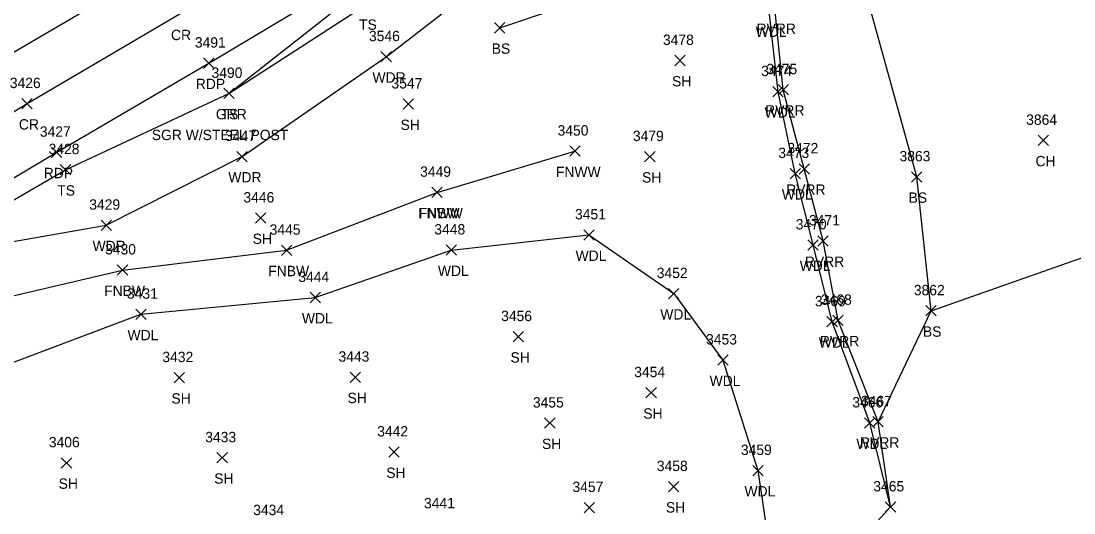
# Model space of a CAD drawing. Extents: x 1443590 to 1445966, y 578314 to 580556.
# Drawn here: x 1444092.8 to 1444295.6, y 578792.7 to 578887.6 of the extents above; entities that cross this region are included whole.
import ezdxf

# ---------------------------------------------------------------- set-up
doc = ezdxf.new("R2010")
doc.units = 0
for name, color, linetype in [('L_A', 7, 'Continuous'), ('L_I', 7, 'Continuous'), ('L_TIC', 7, 'Continuous'), ('LAWA', 7, 'Continuous'), ('LAWE', 7, 'Continuous'), ('LELB', 7, 'Continuous'), ('LFNC', 7, 'Continuous'), ('LSOGP', 7, 'Continuous'), ('P_A', 7, 'Continuous'), ('P_I', 7, 'Continuous'), ('P_TIC', 7, 'Continuous'), ('PET', 7, 'Continuous'), ('PRC', 7, 'Continuous'), ('R_A', 7, 'Continuous'), ('R_C', 7, 'Continuous'), ('R_I', 7, 'Continuous'), ('R_TIC', 7, 'Continuous'), ('RGR', 7, 'Continuous')]:
    doc.layers.add(name, color=color, linetype=linetype)

msp = doc.modelspace()

# ---------------------------------------------------------------- linework, layer by layer
at = {"layer": 'L_TIC'}
for points in [[(1444184, 578885.29), (1444186, 578887.29)], [(1444186, 578885.29), (1444184, 578887.29)], [(1444162.11, 578879.72), (1444164.11, 578881.72)], [(1444164.11, 578879.72), (1444162.11, 578881.72)], [(1444218.69, 578878.99), (1444220.69, 578880.99)], [(1444220.69, 578878.99), (1444218.69, 578880.99)], [(1444131.81, 578872.64), (1444133.81, 578874.64)], [(1444133.81, 578872.64), (1444131.81, 578874.64)], [(1444237.61, 578872.98), (1444239.61, 578874.98)], [(1444239.61, 578872.98), (1444237.61, 578874.98)], [(1444238.61, 578873.35), (1444240.61, 578875.35)], [(1444240.61, 578873.35), (1444238.61, 578875.35)], [(1444166.39, 578870.59), (1444168.39, 578872.59)], [(1444168.39, 578870.59), (1444166.39, 578872.59)], [(1444288.72, 578863.58), (1444290.72, 578865.58)], [(1444290.72, 578863.58), (1444288.72, 578865.58)], [(1444134.34, 578860.47), (1444136.34, 578862.47)], [(1444136.34, 578860.47), (1444134.34, 578862.47)], [(1444198.47, 578861.51), (1444200.47, 578863.51)], [(1444200.47, 578861.51), (1444198.47, 578863.51)], [(1444212.91, 578860.45), (1444214.91, 578862.45)], [(1444214.91, 578860.45), (1444212.91, 578862.45)], [(1444100.33, 578857.93), (1444102.33, 578859.93)], [(1444102.33, 578857.93), (1444100.33, 578859.93)], [(1444242.67, 578858.09), (1444244.67, 578860.09)], [(1444244.67, 578858.09), (1444242.67, 578860.09)], [(1444240.92, 578857.18), (1444242.92, 578859.18)], [(1444242.92, 578857.18), (1444240.92, 578859.18)], [(1444264.32, 578856.54), (1444266.32, 578858.54)], [(1444266.32, 578856.54), (1444264.32, 578858.54)], [(1444171.92, 578853.56), (1444173.92, 578855.56)], [(1444173.92, 578853.56), (1444171.92, 578855.56)], [(1444171.92, 578853.56), (1444173.92, 578855.56)], [(1444173.92, 578853.56), (1444171.92, 578855.56)], [(1444137.91, 578848.6), (1444139.91, 578850.6)], [(1444139.91, 578848.6), (1444137.91, 578850.6)], [(1444108.18, 578847.22), (1444110.18, 578849.22)], [(1444110.18, 578847.22), (1444108.18, 578849.22)], [(1444201.18, 578845.34), (1444203.18, 578847.34)], [(1444203.18, 578845.34), (1444201.18, 578847.34)], [(1444244.36, 578843.41), (1444246.36, 578845.41)], [(1444246.36, 578843.41), (1444244.36, 578845.41)], [(1444246.27, 578844.18), (1444248.27, 578846.18)], [(1444248.27, 578844.18), (1444246.27, 578846.18)], [(1444142.92, 578842.39), (1444144.92, 578844.39)], [(1444144.92, 578842.39), (1444142.92, 578844.39)], [(1444174.65, 578842.43), (1444176.65, 578844.43)], [(1444176.65, 578842.43), (1444174.65, 578844.43)], [(1444111.31, 578838.58), (1444113.31, 578840.58)], [(1444113.31, 578838.58), (1444111.31, 578840.58)], [(1444148.45, 578833.28), (1444150.45, 578835.28)], [(1444150.45, 578833.28), (1444148.45, 578835.28)], [(1444217.5, 578834.02), (1444219.5, 578836.02)], [(1444219.5, 578834.02), (1444217.5, 578836.02)], [(1444114.87, 578830.04), (1444116.87, 578832.04)], [(1444116.87, 578830.04), (1444114.87, 578832.04)], [(1444267.08, 578830.71), (1444269.08, 578832.71)], [(1444269.08, 578830.71), (1444267.08, 578832.71)], [(1444248.03, 578828.59), (1444250.03, 578830.59)], [(1444250.03, 578828.59), (1444248.03, 578830.59)], [(1444249.17, 578828.87), (1444251.17, 578830.87)], [(1444251.17, 578828.87), (1444249.17, 578830.87)], [(1444187.57, 578825.72), (1444189.57, 578827.72)], [(1444189.57, 578825.72), (1444187.57, 578827.72)], [(1444227, 578821.21), (1444229, 578823.21)], [(1444229, 578821.21), (1444227, 578823.21)], [(1444122.25, 578817.81), (1444124.25, 578819.81)], [(1444124.25, 578817.81), (1444122.25, 578819.81)], [(1444156.18, 578817.9), (1444158.18, 578819.9)], [(1444158.18, 578817.9), (1444156.18, 578819.9)], [(1444213.16, 578814.91), (1444215.16, 578816.91)], [(1444215.16, 578814.91), (1444213.16, 578816.91)], [(1444193.64, 578809.05), (1444195.64, 578811.05)], [(1444195.64, 578809.05), (1444193.64, 578811.05)], [(1444255.27, 578809.07), (1444257.27, 578811.07)], [(1444257.27, 578809.07), (1444255.27, 578811.07)], [(1444256.89, 578809.31), (1444258.89, 578811.31)], [(1444258.89, 578809.31), (1444256.89, 578811.31)], [(1444163.64, 578803.47), (1444165.64, 578805.47)], [(1444165.64, 578803.47), (1444163.64, 578805.47)], [(1444100.52, 578801.38), (1444102.52, 578803.38)], [(1444102.52, 578801.38), (1444100.52, 578803.38)], [(1444130.51, 578802.36), (1444132.51, 578804.36)], [(1444132.51, 578802.36), (1444130.51, 578804.36)], [(1444233.72, 578799.9), (1444235.72, 578801.9)], [(1444235.72, 578799.9), (1444233.72, 578801.9)], [(1444217.51, 578796.8), (1444219.51, 578798.8)], [(1444219.51, 578796.8), (1444217.51, 578798.8)], [(1444201.26, 578792.76), (1444203.26, 578794.76)], [(1444203.26, 578792.76), (1444201.26, 578794.76)], [(1444259.27, 578792.87), (1444261.27, 578794.87)], [(1444261.27, 578792.87), (1444259.27, 578794.87)]]:
    msp.add_lwpolyline(points, dxfattribs=at)
at = {"layer": 'LAWA'}
for points in [[(1444048.1, 578821.32), (1444063.67, 578832.31), (1444080.37, 578840.96), (1444085.34, 578844.04), (1444109.18, 578848.22), (1444135.34, 578861.47), (1444163.11, 578880.72), (1444179.57, 578893.49), (1444193.41, 578903.29), (1444214.9, 578918.81), (1444217.38, 578923.7), (1444222.65, 578929.51), (1444230.19, 578931.19), (1444234.32, 578936.96), (1444238.17, 578925.12), (1444234.94, 578915.96)], [(1444260.27, 578793.87), (1444256.27, 578810.07), (1444249.03, 578829.59), (1444245.36, 578844.41), (1444241.92, 578858.18), (1444238.61, 578873.98), (1444236.87, 578889.53), (1444235.77, 578897.72), (1444234.94, 578915.96)], [(1444048.1, 578821.32), (1444049.15, 578815.65), (1444053.76, 578808.6), (1444089.15, 578821), (1444115.87, 578831.04), (1444149.45, 578834.28), (1444175.65, 578843.43), (1444202.18, 578846.34), (1444218.5, 578835.02), (1444228, 578822.21), (1444234.72, 578800.9), (1444237.58, 578781.4), (1444240.48, 578772.04)]]:
    msp.add_lwpolyline(points, dxfattribs=at)
at = {"layer": 'LAWE'}
msp.add_lwpolyline([(1444257.89, 578810.31), (1444250.17, 578829.87), (1444247.27, 578845.18), (1444243.67, 578859.09), (1444239.61, 578874.35), (1444237.96, 578890.11), (1444237.64, 578898.76), (1444236.72, 578915.57)], dxfattribs=at)
at = {"layer": 'LELB'}
for points in [[(1443615.53, 578549.09), (1443647.15, 578571.87), (1443656.71, 578577.24), (1443699.78, 578605.86), (1443739.16, 578631.36), (1443774.01, 578653.63), (1443806.33, 578675.43), (1443846.66, 578699.7), (1443880.84, 578720.78), (1443915.45, 578744.08), (1443953.64, 578767.01), (1443986.4, 578787.39), (1444018.89, 578809.07), (1444030.21, 578814.65), (1444042.78, 578823.31), (1444045.84, 578825.91), (1444071.11, 578843.04), (1444083.63, 578848.63), (1444101.33, 578858.93), (1444132.81, 578873.64), (1444159.48, 578890.92), (1444189.04, 578910.16), (1444210.73, 578922.71), (1444214.87, 578926.32)], [(1444268.08, 578831.71), (1444265.32, 578857.54), (1444253.49, 578900.55), (1444252.71, 578922.32)], [(1444185, 578886.29), (1444205.85, 578893.37), (1444228, 578905.56)]]:
    msp.add_lwpolyline(points, dxfattribs=at)
at = {"layer": 'LFNC'}
for points in [[(1444172.92, 578854.56), (1444199.47, 578862.51)], [(1444049.15, 578815.65), (1444081.82, 578832.41), (1444112.31, 578839.58), (1444143.92, 578843.39), (1444172.92, 578854.56)]]:
    msp.add_lwpolyline(points, dxfattribs=at)
at = {"layer": 'LSOGP'}
msp.add_lwpolyline([(1444240.48, 578772.03), (1444260.27, 578793.87), (1444257.89, 578810.31), (1444268.08, 578831.71), (1444302.21, 578843.7), (1444333.75, 578853.69), (1444366.19, 578868.58), (1444390.03, 578873.32), (1444408.42, 578877.3), (1444432.82, 578879.55), (1444440.78, 578881.29), (1444452.26, 578899.57), (1444453.76, 578899.89), (1444465.48, 578904.32), (1444466.91, 578904.85), (1444478.03, 578909.58), (1444486.22, 578912.8), (1444500.2, 578917.5), (1444513.61, 578923.74), (1444542.19, 578934.76), (1444577.58, 578947.71)], dxfattribs=at)
at = {"layer": 'P_TIC'}
for points in [[(1444127.94, 578878.48), (1444129.94, 578880.48)], [(1444129.94, 578878.48), (1444127.94, 578880.48)], [(1444092.92, 578870.67), (1444094.92, 578872.67)], [(1444094.92, 578870.67), (1444092.92, 578872.67)], [(1444098.65, 578861.29), (1444100.65, 578863.29)], [(1444100.65, 578861.29), (1444098.65, 578863.29)]]:
    msp.add_lwpolyline(points, dxfattribs=at)
at = {"layer": 'PET'}
for points in [[(1443601.36, 578573.38), (1443632.23, 578593.39), (1443639.99, 578598.09), (1443685.58, 578628.02), (1443724.74, 578653.09), (1443761.98, 578676.74), (1443793.7, 578697.2), (1443832.46, 578722.27), (1443867.74, 578744.22), (1443903.66, 578767.03), (1443939.74, 578789.58), (1443974.31, 578811.25), (1444005.54, 578830.37), (1444024.78, 578842.02), (1444070.83, 578869.64), (1444088.82, 578880.14), (1444118.02, 578897.28), (1444147.48, 578914.76), (1444176.13, 578931.32), (1444203.82, 578947.29), (1444208.88, 578939.04), (1444214.07, 578930.35)], [(1443612.4, 578554.37), (1443645.04, 578575.45), (1443657.24, 578583.2), (1443697.44, 578609.18), (1443737.28, 578634.55), (1443772.29, 578657.29), (1443804.75, 578678.07), (1443844.06, 578703.73), (1443878.04, 578725.08), (1443913.76, 578747.61), (1443950.95, 578770.86), (1443984.55, 578791.67), (1444017.37, 578812.19), (1444029.71, 578820.04), (1444042.88, 578828.09), (1444081.78, 578851.73), (1444099.65, 578862.29), (1444128.94, 578879.48), (1444156.82, 578896.17), (1444186.94, 578914.09), (1444214.07, 578930.35)]]:
    msp.add_lwpolyline(points, dxfattribs=at)
at = {"layer": 'PRC'}
msp.add_lwpolyline([(1443607.19, 578563.71), (1443645.74, 578588.68), (1443691.8, 578618.64), (1443730.92, 578643.94), (1443766.58, 578667.23), (1443799.08, 578688.06), (1443838.06, 578712.83), (1443872.72, 578734.91), (1443908.54, 578757.41), (1443944.72, 578780.26), (1443979.55, 578801.84), (1444011.31, 578821.61), (1444031.47, 578833.87), (1444076.05, 578860.79), (1444093.92, 578871.67), (1444123.23, 578888.92), (1444152.19, 578905.95), (1444180.96, 578922.73), (1444208.88, 578939.04)], dxfattribs=at)
at = {"layer": 'R_TIC'}
for points in [[(1444131.81, 578872.64), (1444133.81, 578874.64)], [(1444133.81, 578872.64), (1444131.81, 578874.64)]]:
    msp.add_lwpolyline(points, dxfattribs=at)
at = {"layer": 'RGR'}
msp.add_lwpolyline([(1444132.81, 578873.64), (1444157.74, 578893.28), (1444187.55, 578912.85), (1444214.24, 578929.82)], dxfattribs=at)

# ---------------------------------------------------------------- texts
at = {"layer": 'L_A'}
for s, p in [('TS', (1444157.89, 578885.92)), ('WDL', (1444234.29, 578884.53)), ('RVRR', (1444234.47, 578885.11)), ('BS', (1444183.44, 578881.29)), ('WDR', (1444160.47, 578875.72)), ('SH', (1444218.18, 578874.99)), ('TS', (1444131.22, 578868.64)), ('WDL', (1444236.02, 578868.98)), ('RVRR', (1444236.13, 578869.35)), ('SH', (1444165.88, 578866.59)), ('CH', (1444288.21, 578859.58)), ('WDR', (1444132.7, 578856.47)), ('FNWW', (1444195.82, 578857.51)), ('SH', (1444212.4, 578856.45)), ('TS', (1444099.74, 578853.93)), ('RVRR', (1444240.18, 578854.09)), ('WDL', (1444239.34, 578853.18)), ('BS', (1444263.76, 578852.54)), ('FNWW', (1444169.27, 578849.56)), ('FNBW', (1444169.39, 578849.56)), ('SH', (1444137.4, 578844.6)), ('WDR', (1444106.54, 578843.22)), ('WDL', (1444199.6, 578841.34)), ('WDL', (1444242.78, 578839.41)), ('RVRR', (1444243.78, 578840.18)), ('FNBW', (1444140.39, 578838.39)), ('WDL', (1444173.07, 578838.43)), ('FNBW', (1444108.78, 578834.58)), ('WDL', (1444146.87, 578829.28)), ('WDL', (1444215.92, 578830.02)), ('WDL', (1444113.28, 578826.04)), ('BS', (1444266.52, 578826.71)), ('WDL', (1444246.45, 578824.59)), ('RVRR', (1444246.68, 578824.87)), ('SH', (1444187.06, 578821.72)), ('WDL', (1444225.42, 578817.21)), ('SH', (1444121.74, 578813.81)), ('SH', (1444155.67, 578813.9)), ('SH', (1444212.65, 578810.91)), ('SH', (1444193.13, 578805.05)), ('WDL', (1444253.69, 578805.07)), ('RVRR', (1444254.4, 578805.31)), ('SH', (1444163.13, 578799.47)), ('SH', (1444100.01, 578797.38)), ('SH', (1444129.99, 578798.36)), ('WDL', (1444232.14, 578795.9)), ('SH', (1444217, 578792.8))]:
    msp.add_text(s, height=2, dxfattribs=at).set_placement(p)
at = {"layer": 'L_I'}
for s, p in [('3546', (1444159.79, 578883.72)), ('3478', (1444216.43, 578882.99)), ('3490', (1444129.46, 578876.64)), ('3474', (1444235.35, 578876.98)), ('3475', (1444236.35, 578877.35)), ('3547', (1444164.13, 578874.59)), ('3864', (1444286.41, 578867.58)), ('3447', (1444132.08, 578864.47)), ('3450', (1444196.13, 578865.51)), ('3479', (1444210.64, 578864.45)), ('3428', (1444098.07, 578861.93)), ('3472', (1444240.41, 578862.09)), ('3473', (1444238.66, 578861.18)), ('3863', (1444262.01, 578860.54)), ('3449', (1444169.65, 578857.56)), ('3449', (1444169.65, 578857.56)), ('3446', (1444135.6, 578852.6)), ('3429', (1444105.91, 578851.22)), ('3451', (1444199.49, 578849.34)), ('3470', (1444242.02, 578847.41)), ('3471', (1444244.57, 578848.18)), ('3445', (1444140.66, 578846.39)), ('3448', (1444172.39, 578846.43)), ('3430', (1444108.96, 578842.58)), ('3444', (1444146.19, 578837.28)), ('3452', (1444215.24, 578838.02)), ('3431', (1444113.17, 578834.04)), ('3862', (1444264.77, 578834.71)), ('3469', (1444245.71, 578832.59)), ('3468', (1444246.87, 578832.87)), ('3456', (1444185.26, 578829.72)), ('3453', (1444224.74, 578825.21)), ('3432', (1444119.99, 578821.81)), ('3443', (1444153.92, 578821.9)), ('3454', (1444210.9, 578818.91)), ('3455', (1444191.38, 578813.05)), ('3466', (1444252.91, 578813.07)), ('3467', (1444254.59, 578813.31)), ('3442', (1444161.38, 578807.47)), ('3406', (1444098.12, 578805.38)), ('3433', (1444128.25, 578806.36)), ('3459', (1444231.45, 578803.9)), ('3458', (1444215.25, 578800.8)), ('3457', (1444199, 578796.76)), ('3465', (1444256.96, 578796.87)), ('3441', (1444170.39, 578793.62)), ('3434', (1444137.49, 578792.3))]:
    msp.add_text(s, height=2, dxfattribs=at).set_placement(p)
at = {"layer": 'P_A'}
for s, p in [('CR', (1444121.66, 578883.92)), ('RDP', (1444126.43, 578874.48)), ('CR', (1444092.35, 578866.67)), ('RDP', (1444097.14, 578857.29))]:
    msp.add_text(s, height=2, dxfattribs=at).set_placement(p)
at = {"layer": 'P_I'}
for s, p in [('3491', (1444126.25, 578882.48)), ('3426', (1444090.6, 578874.67)), ('3427', (1444096.39, 578865.29))]:
    msp.add_text(s, height=2, dxfattribs=at).set_placement(p)
at = {"layer": 'R_A'}
msp.add_text('GRR', height=2, dxfattribs=at).set_placement((1444130.3, 578868.64))
at = {"layer": 'R_C'}
msp.add_text('SGR W/STEEL POST', height=2, dxfattribs=at).set_placement((1444117.95, 578864.64))
at = {"layer": 'R_I'}
msp.add_text('3490', height=2, dxfattribs=at).set_placement((1444129.46, 578876.64))

doc.saveas('drawing.dxf')
